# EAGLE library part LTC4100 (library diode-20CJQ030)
Linear's LTC4100 Smart Battery Charger Controller Description: The LTC®4100 Smart Battery Charger is a single chip charging solution that dramatically simplifies construction of an SBS compliant system. The LTC4100 implements a Level 2 charger function whereby the charger can be programmed by the battery or by the host. A SafetySignal on the battery being charged is monitored for temperature, connectivity and battery type information. The SMBus interface remains alive when the AC power adapter is removed and responds to all SMBus activity directed to it, including SafetySignal status (via the ChargerStatus command). The charger also provides an interrupt to the host whenever a status change is detected (e.g., battery removal, AC adapter connection). Charging current and voltage are restricted to chemistryspecific limits for improved system safety and reliability. Limits are programmable by two external resistors. Additionally, the maximum average current from the AC adapter is programmable to avoid overloading the adapter when simultaneously supplying load current and charging current. When supplying system load current, charging current is automatically reduced to prevent adapter overload. Features: Single Chip Smart Battery Charger Controller 100% Compliant (Rev. 1.1) SMBus Support Allows for Operation with or without Host SMBus Accelerator Improves SMBus Timing Wide Output Voltage Range: 3.5V to 26V Hardware Interrupt and SMBAlert Response Eliminate Interrupt Polling High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
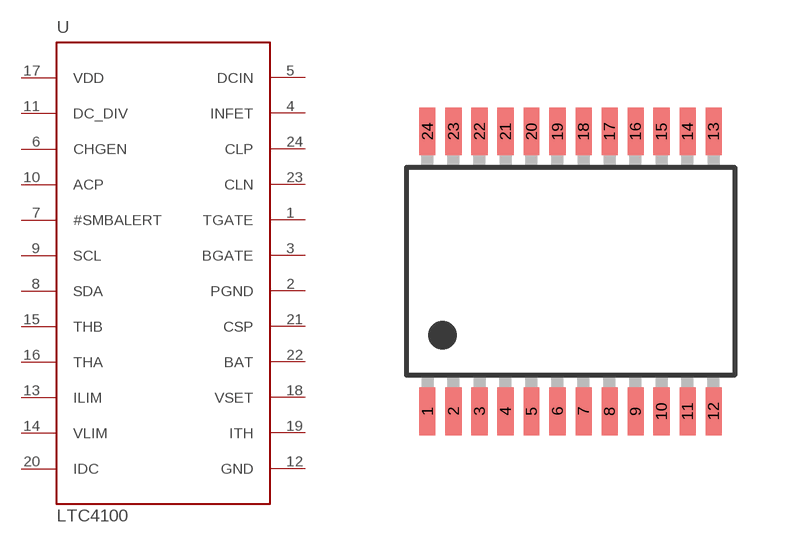
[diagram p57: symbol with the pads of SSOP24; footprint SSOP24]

Designator prefix U

## LTC4100  [SSOP24]
1  TGATE  out
2  PGND  pwr
3  BGATE  out
4  INFET  out
5  DCIN  in
6  CHGEN  out
7  #SMBALERT  out
8  SDA
9  SCL
10  ACP  out
11  DC_DIV  in
12  GND  pwr
13  ILIM  in
14  VLIM  in
15  THB  out
16  THA  out
17  VDD  pwr
18  VSET  in
19  ITH  in
20  IDC  in
21  CSP  in
22  BAT  in
23  CLN  in
24  CLP  in

## Footprint SSOP24 (pad centres in mm)
SSOP 24 E.g: LTC4100
smd 0.4 x 1.2: 1 -3.575,-3.5; 2 -2.925,-3.5; 3 -2.275,-3.5; 4 -1.625,-3.5; 5 -0.975,-3.5; 6 -0.325,-3.5; 7 0.325,-3.5; 8 0.975,-3.5; 9 1.625,-3.5; 10 2.275,-3.5; 11 2.925,-3.5; 12 3.575,-3.5; 13 3.575,3.5; 14 2.925,3.5; 15 2.275,3.5; 16 1.625,3.5; 17 0.975,3.5; 18 0.325,3.5; 19 -0.325,3.5; 20 -0.975,3.5; 21 -1.625,3.5; 22 -2.275,3.5; 23 -2.925,3.5; 24 -3.575,3.5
